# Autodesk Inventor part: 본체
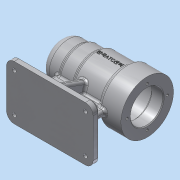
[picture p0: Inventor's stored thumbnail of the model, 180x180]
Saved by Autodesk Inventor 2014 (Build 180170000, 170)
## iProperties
Created: 2016-06
Part Number: 본체
Material: 알루미늄 6061
Document SubType Name: Modeling
Designer: 406-017
Density: 2.71 g/cm^3
Appearance: 알루미늄 - 평지
Mass: 624.755 g
Surface Area: 673.705 cm^2
Volume: 230.537 cm^3
Author: 406-017
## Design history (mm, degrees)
sketch "스케치1"
  geometry: L1 (0, 0)-(0, 25); L2 (0, 25)-(25, 25); L3 (25, 25)-(25, 27); L4 (25, 27)-(45, 27); L5 (45, 27)-(45, 30); L6 (45, 30)-(84, 30); L7 (84, 30)-(84, 34); L8 (84, 34)-(112, 34); L9 (112, 34)-(112, 0); L10 (112, 0)-(0, 0)
  constraints: 20 end point, 6 parallel, 2 perpendicular, 2 vertical
  dimensions: "d0" = 112 distance between parallel lines of L9 L1; "d1" = 50 diameter of L2 L10; "d2" = 54 diameter of L4 L10; "d4" = 60 diameter of L6 L10; "d5" = 68 diameter of L8 L10; "d6" = 25 distance of L1.end L2.end; "d7" = 45 distance between parallel lines of L5 L1; "d8" = 84 distance between parallel lines of L7 L1
revolve "회전1" sketch "스케치1" stored, may be unused: angle "d9" = 90 deg
sketch "스케치2"
  geometry: L1 (25, -25)-(0, -25) reference; L2 (0, -25)-(0, 25) reference; L3 (0, 25)-(25, 25) reference; L4 (25, 25)-(25, 27) reference; L5 (25, 27)-(45, 27) reference; L6 (45, 27)-(45, 30) reference; L7 (45, 30)-(84, 30) reference; L8 (84, 30)-(84, 34) reference; L9 (84, 34)-(112, 34) reference; L10 (112, 34)-(112, -34) reference; L11 (112, -34)-(84, -34) reference; L12 (84, -34)-(84, -30) reference; L13 (84, -30)-(45, -30) reference; L14 (45, -30)-(45, -27) reference; L15 (45, -27)-(25, -27) reference; L16 (25, -27)-(25, -25) reference; L17 (0, 0)-(112, 0); L18 (6, 0)-(6, 7.5); L19 (9, 10.5)-(9, 10.5); L20 (9, 10.5)-(9, 15.7); L21 (9.3, 16)-(13, 16); L22 (13, 16)-(13, 17.2); L23 (13.3, 17.5)-(31, 17.5); L24 (31, 17.5)-(31, 20.7); L25 (31.3, 21)-(43, 21); L26 (43, 21)-(43, 21); L27 (46, 24)-(94, 24); L28 (97, 21)-(97, 21); L29 (97, 21)-(112, 21); L30 (112, 0)-(112, 21); A1 r 0.3 centre (9.3, 15.7) between (9.3, 16) and (9, 15.7); A2 r 0.3 centre (13.3, 17.2) between (13.3, 17.5) and (13, 17.2); A3 r 0.3 centre (31.3, 20.7) between (31.3, 21) and (31, 20.7); A4 r 3 centre (46, 21) between (46, 24) and (43, 21); A5 r 3 centre (94, 21) between (97, 21) and (94, 24); A6 r 3 centre (9, 7.5) between (9, 10.5) and (6, 7.5); 6 further points
  constraints: 28 end point, 14 point on line, 12 point on circle, 12 tangent, 6 centre point, 6 perpendicular, 5 parallel, 2 equal radius, 1 collinear, 1 midpoint, 1 vertical
  dimensions: "d10" = 15 distance of L28.end L29.end; "d11" = 54 distance of point (43, 24) point (97, 24); "d12" = 42 diameter of L29 L17; "d13" = 48 diameter of L27 L17; "d14" = 12 distance of point (31, 21) L25.end; "d15" = 18 distance of point (13, 17.5) L23.end; "d16" = 4 distance of point (9, 16) L21.end; "d17" = 3 distance of point (6, 10.5) L19.end; "d18" = 42 diameter of L25 L17; "d19" = 35 diameter of L23 L17; "d20" = 32 diameter of L21 L17; "d21" = 21 diameter of L19 L17; "d22" = 0.3 radius of A1; "d50" = 3 radius of A4; "d85" = 3 radius of A5; "d105" = 3 radius of A6
revolve "회전2" sketch "스케치2" stored, may be unused: angle "d23" = 90 deg
node "작업 평면1"
sketch "스케치3"
  geometry: L1 (-112, -35)-(0, -35); L2 (0, -35)-(0, 35); L3 (0, 35)-(-112, 35); L4 (-112, 35)-(-112, -35); L5 (-112, -35)-(0, 35); L6 (0, -35)-(-112, 35); 2 further points
  constraints: 12 end point, 2 midpoint, 2 parallel, 1 horizontal, 1 perpendicular, 1 vertical alignment
  dimensions: "d25" = 112 distance of L2.end L3.end; "d26" = 70 distance of L1.end L2.end; "d27" = 35 distance from line of point (0, 0) L3
extrude "돌출1" join sketch "스케치3" distance "d28" = 10; taper "d29" = 0 deg
sketch "스케치4"
  geometry: L1 (92, -34)-(92, -60); L2 (92, -60)-(20, -60); L3 (20, -60)-(20, -27); L4 (20, -27)-(92, -60); L5 (92, -27)-(20, -60); L6 (112, -70)-(112, -60) reference; L7 (25, -25)-(0, -25) reference; L8 (0, -25)-(0, 25) reference; L9 (0, 25)-(25, 25) reference; L10 (25, 25)-(25, 27) reference; L11 (25, 27)-(45, 27) reference; L12 (45, 27)-(45, 30) reference; L13 (45, 30)-(84, 30) reference; L14 (84, 30)-(84, 34) reference; L15 (84, 34)-(112, 34) reference; L16 (112, 34)-(112, 21) reference; L17 (112, 21)-(97, 21) reference; L18 (94, 24)-(46, 24) reference; L19 (43, 21)-(31.3, 21) reference; L20 (31, 20.7)-(31, 17.5) reference; L21 (31, 17.5)-(13.3, 17.5) reference; L22 (13, 17.2)-(13, 16) reference; L23 (13, 16)-(9.3, 16) reference; L24 (9, 15.7)-(9, 10.5) reference; L25 (9, -10.5)-(9, -15.7) reference; L26 (9.3, -16)-(13, -16) reference; L27 (13, -16)-(13, -17.2) reference; L28 (13.3, -17.5)-(31, -17.5) reference; L29 (31, -17.5)-(31, -20.7) reference; L30 (31.3, -21)-(43, -21) reference; L31 (46, -24)-(94, -24) reference; L32 (97, -21)-(112, -21) reference; L33 (112, -21)-(112, -34) reference; L34 (112, -34)-(84, -34) reference; L35 (84, -34)-(84, -30) reference; L36 (84, -30)-(45, -30) reference; L37 (45, -30)-(45, -27) reference; L38 (45, -27)-(25, -27) reference; L39 (25, -27)-(25, -25) reference; L40 (0, -70)-(0, -60) reference; L41 (0, -60)-(112, -60) reference; L42 (112, -60)-(112, -70) reference; L43 (112, -70)-(0, -70) reference; L44 (20, -27)-(20, -25); L45 (20, -25)-(20, -22); L46 (20, -22)-(41.379, -22); L47 (92, -27)-(92, -34); L48 (41.379, -22)-(45.428, -27); L49 (92, -27)-(45.428, -27); L50 (6, 7.5)-(6, -7.5) reference; A1 r 0.3 centre (31.3, 20.7) between (31.3, 21) and (31, 20.7) reference; A2 r 0.3 centre (13.3, 17.2) between (13.3, 17.5) and (13, 17.2) reference; A3 r 0.3 centre (9.3, 15.7) between (9.3, 16) and (9, 15.7) reference; A4 r 0.3 centre (9.3, -15.7) between (9, -15.7) and (9.3, -16) reference; A5 r 0.3 centre (13.3, -17.2) between (13, -17.2) and (13.3, -17.5) reference; A6 r 0.3 centre (31.3, -20.7) between (31, -20.7) and (31.3, -21) reference; A7 r 3 centre (46, 21) between (46, 24) and (43, 21) reference; A8 r 3 centre (46, -21) between (43, -21) and (46, -24) reference; A9 r 3 centre (94, 21) between (97, 21) and (94, 24) reference; A10 r 3 centre (94, -21) between (94, -24) and (97, -21) reference; A11 r 3 centre (9, 7.5) between (9, 10.5) and (6, 7.5) reference; A12 r 3 centre (9, -7.5) between (6, -7.5) and (9, -10.5) reference; 3 further points
  constraints: 22 end point, 3 point on line, 2 horizontal alignment, 2 midpoint, 2 perpendicular, 1 collinear, 1 parallel, 1 vertical alignment
  dimensions: "d30" = 56 distance from line of point (56, -43.5) L6; "d31" = 20 distance between parallel lines of L1 L6; "d92" = 20 distance between parallel lines of L3 L40; "d95" = 38 distance between parallel lines of L2 L46; "d97" = 129 deg angle of L49 L48; "d98" = 90 deg angle of L47 L49; "d99" = 21.3788 distance of L45.end L46.end; "d100" = 38 distance from line of L41 L46.end; "d101" = 46.57228 distance of L47.start L48.end
extrude "돌출2" join sketch "스케치4" stored distance "d34" = 8; taper "d35" = 0 deg
node "작업 평면2"
sketch "스케치5"
  geometry: L1 (35, -60)-(35, -70) reference; L2 (35, -70)-(-35, -70) reference; L3 (-35, -70)-(-35, -60) reference; L4 (-35, -60)-(-4, -60) reference; L5 (-4, -60)-(-4, -29.732) reference; L6 (4, -29.732)-(4, -60) reference; L7 (4, -60)-(35, -60) reference; L8 (-28, -60)-(-15.509, -25.68); C1 r 24 at (0, 0) reference; A1 r 30 centre (0, 0) between (4, -29.732) and (-4, -29.732) reference; 1 further point
  constraints: 2 end point, 1 point on circle, 1 point on line
  dimensions: "d37" = 7 distance from line of L8.start L3; "d39" = 110 deg angle of L4 L8
feature "리브1" sketch "스케치5" dims "d40" = 1, "d41" = 8, "d42" = 0, "d43" = 0, "d44" = 1, "d45" = 1
fillet "모깎기1" dims "d46" = 10
chamfer "모따기1" distance "d47" = 4; stored, may be unused: second distance "d48" = 2, angle "d49" = 45 deg
hole "구멍1" diameter "d53" = 5; stored, may be unused: countersink angle "d57" = 90 deg, drill point angle "d59" = 118 deg; dims "d51" = 10, "d52" = 10, "d54" = 6, "d55" = 9, "d56" = 4, "d58" = 8
sketch "스케치6" dims "d66" = 52
  geometry: C1 r 21 at (0, 0) reference; C2 r 34 at (0, 0) reference; 2 further points
  constraints: 2 vertical alignment, 1 coincident, 2 other
hole "구멍2" sketch "스케치6" at (0, 26) diameter "d67" = 3.242; stored, may be unused: countersink angle "d71" = 90 deg, drill point angle "d73" = 118 deg; dims "d68" = 8, "d69" = 9, "d70" = 4, "d72" = 11
node "작업 평면3"
sketch "스케치7"
  geometry: L1 (47.5, -34)-(47.5, 34) reference; L2 (-17.03, 2.456)-(16.153, 2.456); L3 (16.153, 2.456)-(16.153, -2.347); L4 (16.153, -2.347)-(-17.03, -2.347); L5 (-17.03, -2.347)-(-17.03, 2.456); 2 further points
  constraints: 1 horizontal alignment, 2 other
  dimensions: "d77" = 48 distance from line of point (-0.5, 0) L1
feature "엠보싱1" sketch "스케치7" dims "d78" = 0.5, "d79" = 0
fillet "모깎기2" dims "d80" = 3, "d81" = 3
fillet "모깎기5" dims "d84" = 3
chamfer "모따기2" distance "d86" = 1; stored, may be unused: second distance "d87" = 2, angle "d88" = 45 deg
fillet "모깎기8" dims "d102" = 3
fillet "모깎기9" dims "d103" = 3
fillet "모깎기10" dims "d104" = 3
node "솔리드1"
mirror "대칭1"
pattern_linear "직사각형 패턴1" dims "d62" = 92
pattern_circular "원형 패턴1" dims angle "d75" = 360 deg
node "절단 모서리 투영1"
node "절단 모서리 투영2"
node "절단 모서리 투영3"
other parameters: "d36" = -56
